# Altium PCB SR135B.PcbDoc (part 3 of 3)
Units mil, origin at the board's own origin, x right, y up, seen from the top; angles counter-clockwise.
Board outline 4100 x 3600 mil, 4 copper layers (Top Layer, Signal Layer 1, Signal Layer 2, Bottom Layer), stack 73.068 mil thick; 169 components, 61 nets, 392 pads, 261 vias.
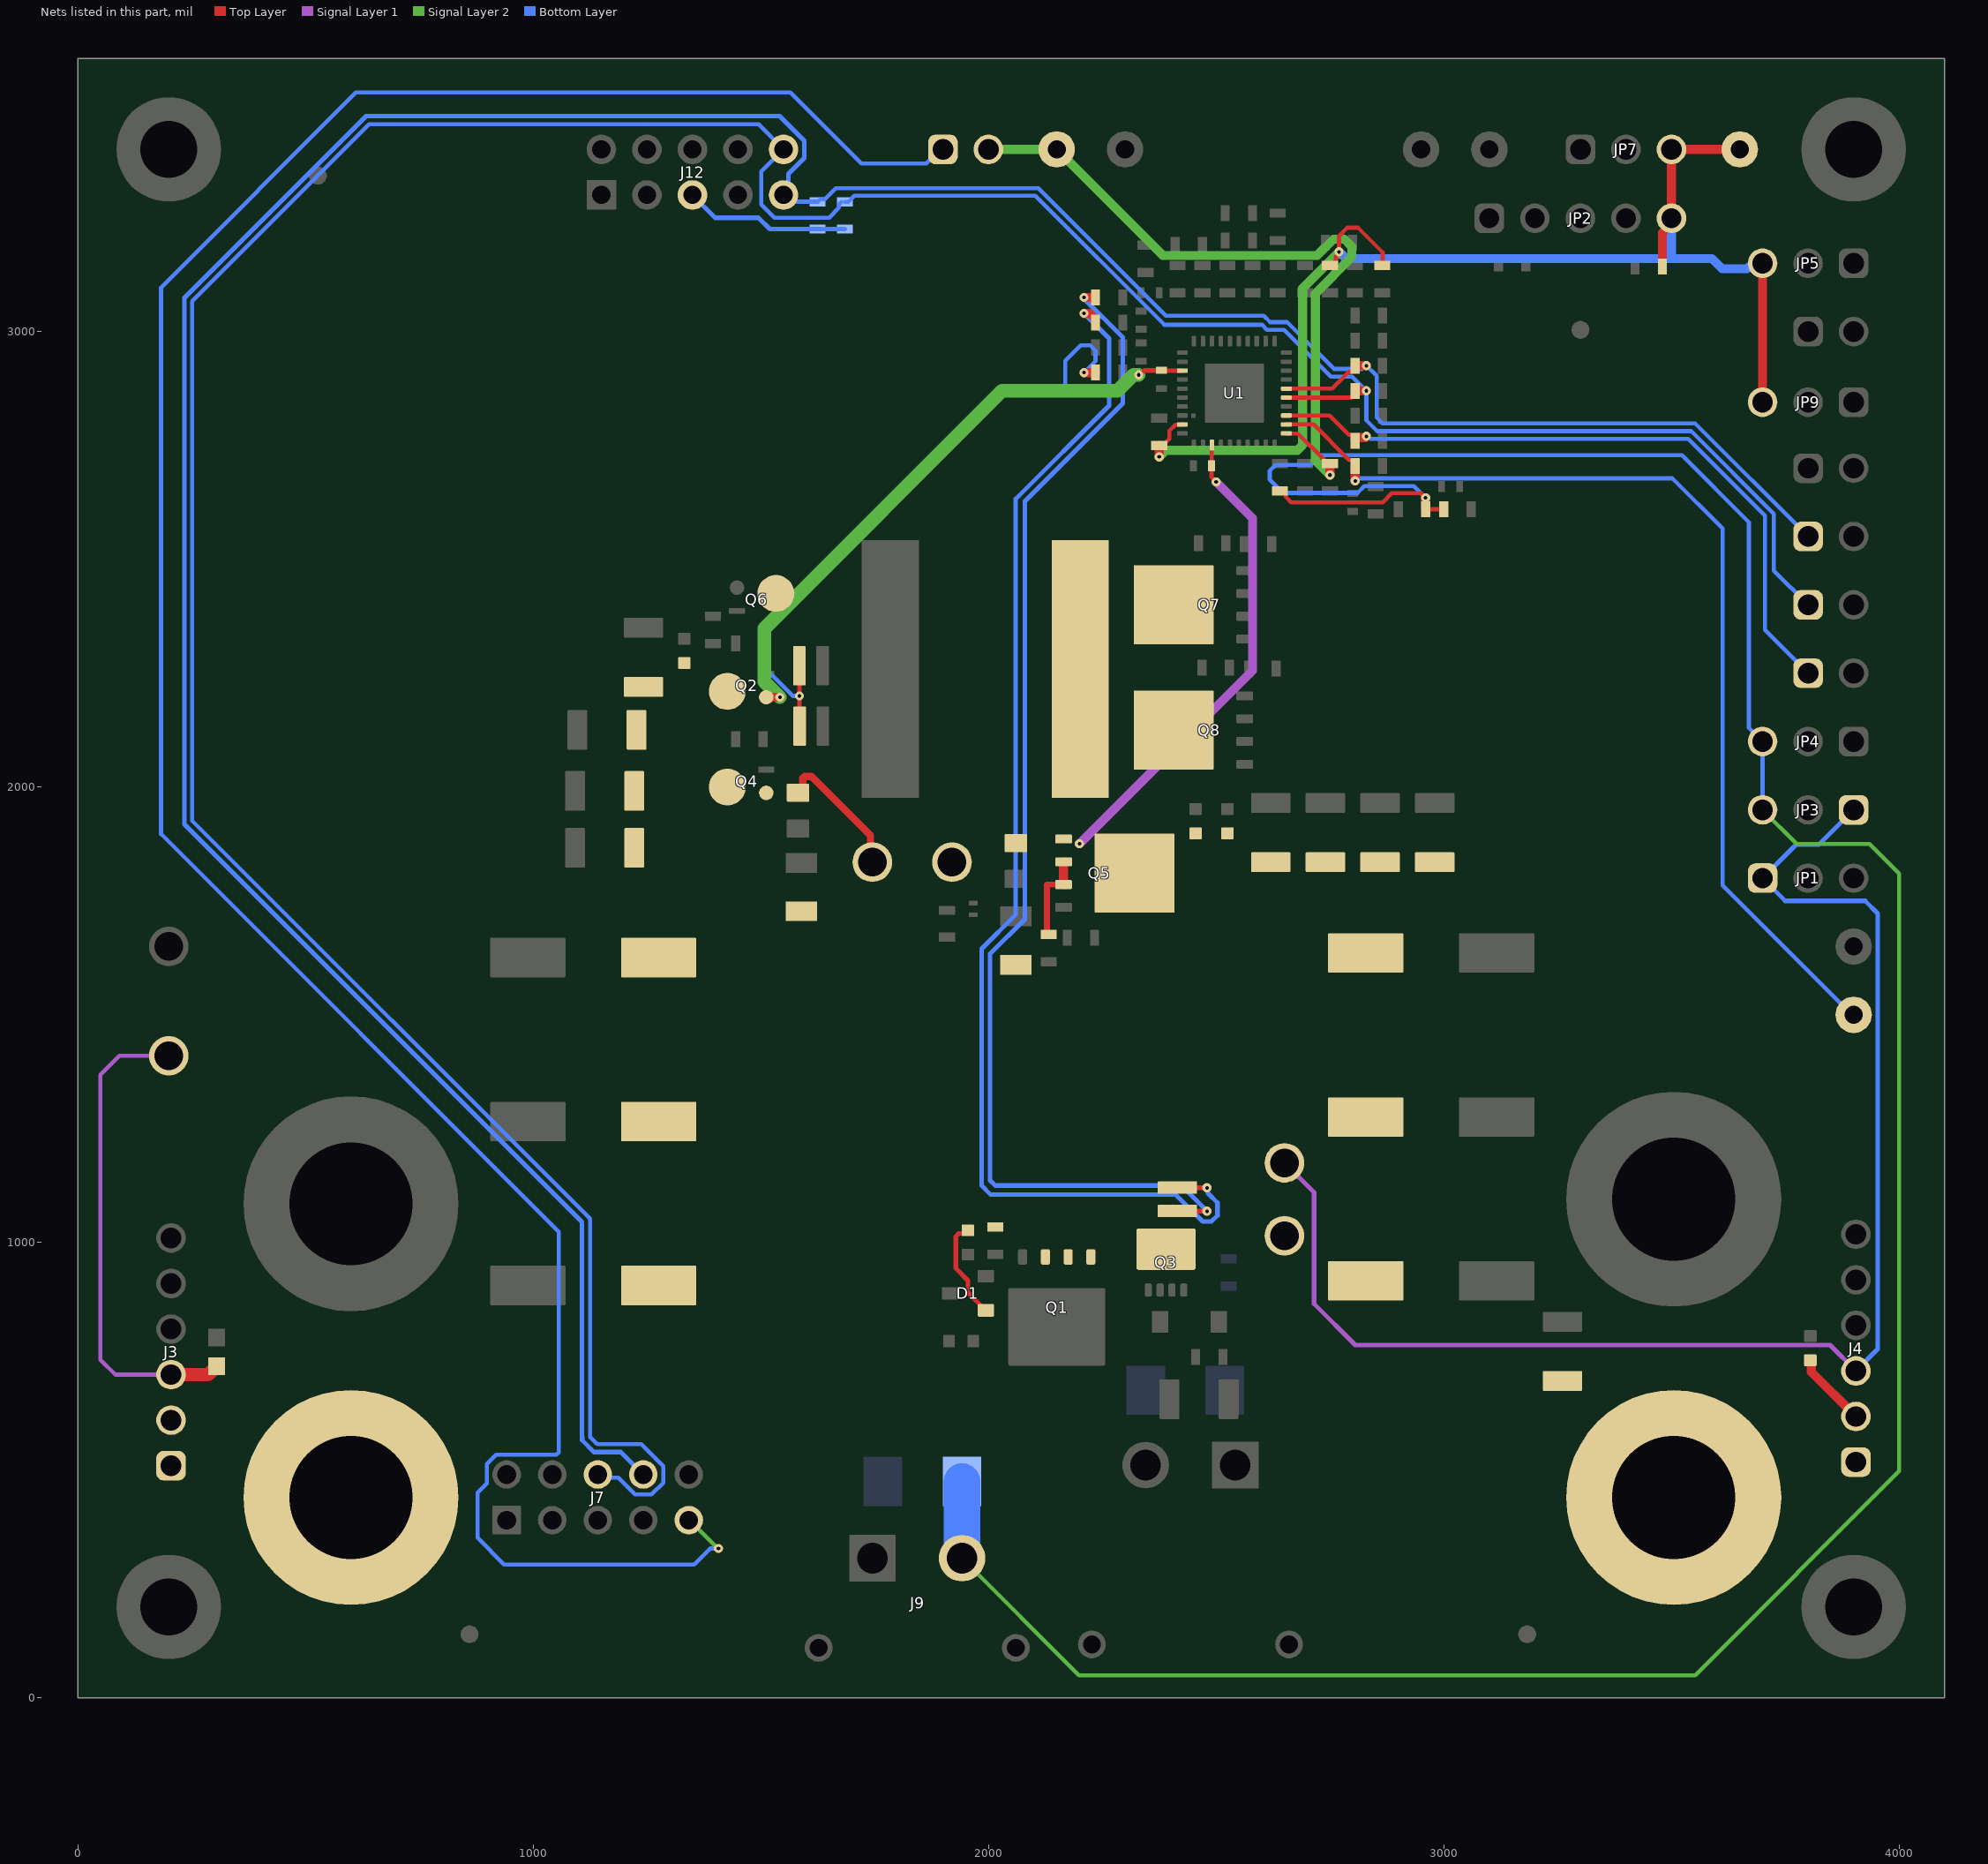
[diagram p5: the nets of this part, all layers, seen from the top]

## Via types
v1: diameter 20, hole 8, Top Layer to Bottom Layer, tented both sides, 241 vias
v2: diameter 19.68, hole 7.87, Top Layer to Bottom Layer, tented both sides, 12 vias
v3: diameter 24, hole 8, Top Layer to Bottom Layer, tented both sides, 7 vias
v4: diameter 34, hole 16, Top Layer to Bottom Layer, tented both sides, 1 vias

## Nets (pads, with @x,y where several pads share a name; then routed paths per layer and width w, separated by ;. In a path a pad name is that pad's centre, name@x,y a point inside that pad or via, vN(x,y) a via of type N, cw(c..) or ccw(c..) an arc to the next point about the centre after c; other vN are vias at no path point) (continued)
SCL: J7.8 J12.9 JP11.1 R39.1 R42.2 U1.6 | length 7567.3
  Top Layer w9: U1.6@2654.17,2874.84 2754.84,2874.84 2792,2912 2799.5,2912 2805,2917.5 R42.2@2805,2925
  Top Layer w20: R42.2@2805,2925 v1(2830,2925)
  Bottom Layer w9: R39.1@1625,3285 1630.5,3290.5 1640.46,3290.5 1664.96,3315 2110,3315 2390,3035 2604.49,3035 2618.74,3020.75 2656.13,3020.75 2758.76,2918.13 2820.15,2918.13 2827.02,2925 v1(2830,2925) 2852.37,2902.63 2852.37,2811.49 2865.62,2798.25 3551.75,2798.25 JP11.1@3800,2550
  Bottom Layer w10: J7.8@1242.09,490.59 1192.68,540 1133.71,540 1107.63,566.09 1107.63,574.5 1107.37,574.75 1107.37,1044.94 234.25,1918.07 234.25,3073.82 633.44,3473.01 1541.13,3473.01 1595.35,3418.79 1595.35,3381.21 1560.52,3346.38 1560.52,3310.52 J12.9@1550,3300 1564.87,3300 1579.87,3285 R39.1@1625,3285
SDA: J7.6 J12.10 JP10.1 R40.1 R41.2 U1.5 | length 7872.1
  Top Layer w9: U1.5@2654.17,2855.16 2797.66,2855.16 2805,2862.5 R41.2@2805,2870
  Top Layer w20: R41.2@2805,2870 v1(2830,2870)
  Bottom Layer w9: J7.6@1142.09,490.59 1148.65,484.03 1186.89,484.03 1224,446.92 1260.18,446.92 1285.76,472.5 1285.76,509.24 1237.63,557.37 1141.87,557.37 1141.12,558.13 1140.16,558.13 1125,573.28 1125,1052.5 251.62,1925.88 251.62,3066.62 640,3455 1495,3455 J12.10@1550,3400 1501.25,3351.25 1501.25,3278.75 1530,3250 1650,3250 1672,3272 1672,3279.5 R40.1@1677.5,3285 ; R40.1@1685,3285 1692.5,3285 1705.63,3298.13 2103.01,3298.13 2386.14,3015 2600.63,3015 2611.75,3003.88 2649.14,3003.88 2751.77,2901.25 2798.75,2901.25 v1(2830,2870) 2830,2805 2853.63,2781.37 3543.63,2781.37 3725,2600 3725,2475 JP10.1@3800,2400
SS/ATRK: C37.1 TP13.1 U1.2 | length 2269.5
  Top Layer w9: U1.2@2654.17,2796.1 2713.9,2796.1 2792,2718 2799.5,2718 2805,2712.5 C37.1@2805,2705
  Top Layer w20: C37.1@2805,2705 2805,2672.72 v1(2805.45,2672.26)
  Bottom Layer w9: v1(2805.45,2672.26) 2808.43,2672.26 2813.93,2677.76 3501.9,2677.76 3612.07,2567.59 3612.07,1784.07 3896.14,1500 TP13.1@3900,1500
SW1: C30.2 C31.1 Q2.1-2-3 Q4.1-2-3 Q6.5-6-7-8 R4.2 R6.2 R17.2 TP5.1 U1.23 | length 3098.9
  Top Layer w10: R6.2@1584.71,2266.3 1585,2266.01 v1(1585,2200) 1585,2133.99 R4.2@1585.29,2133.7 ; TP5.1@1740.79,1839.21 TP5.1@1745,1835 ; v1(2330,2905) 2332.71,2905 2342.33,2914.63 2379.63,2914.63 C31.1@2380,2915 2380.71,2914.29 2425.75,2914.29 U1.23@2425.83,2914.21
  Top Layer w16: C30.2@1581.75,1975.58 1592.42,1986.25 1592.42,2019.27 1596.58,2023.43 1610.87,2023.43 1740.79,1893.5 TP5.1@1740.79,1839.21
  Top Layer w20: Q2.1-2-3@1512.09,2197.2 v1(1542.09,2197.2) ; v1(2210,2910) R17.2@2235,2910
  Signal Layer 2 w30: v1(1542.09,2197.2) 1507.87,2231.42 1507.87,2347.87 2030,2870 2283.51,2870 2318.51,2905 v1(2330,2905)
  Bottom Layer w9: v1@1584.82,2200.18 1569.82,2200.18 1500,2270 1500,2351.97 2027.09,2879.06 2163.35,2879.06 2168.62,2884.34 2168.62,2935.97 2202.65,2970 2223.45,2970 2235,2958.45 2235,2935 v1(2210,2910)
  Bottom Layer w10: v1@1584.82,2200.18 v1(1585,2200)
SW2: C32.2 C33.1 C42.1 L1.2 Q5.1 Q5.2 Q5.3 Q7.5-6-7-8 Q8.5-6-7-8 TP6.1 U1.33 | length 1266.9
  Top Layer w9: U1.33@2490.79,2750.83 2490.39,2750.43 2490.39,2705.39 C33.1@2490,2705 2490,2680.35 2500,2670.35 v1(2500,2670)
  Top Layer w13: C42.1@2128.34,1676.57 2128.34,1785.87 Q5.3@2165.12,1785.87 ; C42.1@2132,1676.23 C42.1@2132.34,1676.57
  Top Layer w20: Q5.3@2165.12,1785.87 Q5.2@2165.12,1835.87
  Signal Layer 1 w20: v1(2200,1875.48) 2580,2255.48 2580,2590 v1(2500,2670)
SYNC: JP6.1 R24.2 U1.3 | length 1536.9
  Top Layer w9: U1.3@2654.17,2815.79 2749.21,2815.79 2792,2773 2799.5,2773 R24.2@2805,2767.5
  Top Layer w20: R24.2@2805,2760 2805,2767.5 2827.5,2767.5 v1(2830,2770)
  Bottom Layer w9: v1(2830,2770) 2832.98,2770 2838.48,2764.5 3536.64,2764.5 3705,2596.14 3705,2345 JP6.1@3800,2250
VBUS: J12.5 R39.2 R40.2 | length 366.1
  Bottom Layer w10: J12.5@1350,3300 1400,3250 1495,3250 1520,3225 R39.2@1625,3225 R40.2@1685,3225
VCC1: C26.2 JP12.2 TP10.1 U1.1 | length 1614.2
  Top Layer w9: U1.1@2654.17,2776.42 2679.48,2776.42 2737,2718.9 2737,2715.5 2742.5,2710 C26.2@2750,2710
  Top Layer w20: v1(2750,2685) C26.2@2750,2710
  Signal Layer 2 w20: JP12.2@2000,3400 TP10.1@2150,3400 2382.87,3167.13 2722.13,3167.13 2757.87,3202.87 2781.55,3202.87 2797.87,3186.55 2797.87,3163.45 2717.87,3083.45 2717.87,2717.13 v1(2750,2685)
VCC1_J: J7.9 JP12.1 | length 5888.6
  Signal Layer 2 w9: J7.9@1342.09,390.59 1343.33,390.59 1405.8,328.13 v1(1407.05,328.13)
  Bottom Layer w9: v1(1407.05,328.13) 1389.11,328.13 1354.11,293.13 936.69,293.13 878.13,351.69 878.13,450.49 898.41,470.78 898.41,513.41 919.26,534.26 1050.73,534.26 1050.98,534.01 1056.25,539.28 1056.25,1023.77 183.13,1896.89 183.13,3096.99 611.14,3525 1565,3525 1721.25,3368.75 1863.48,3368.75 1894.73,3400 JP12.1@1900,3400
VCC2: C27.2 JP2.5 JP5.3 JP7.3 JP9.3 R2.2 R25.2 R36.1 TP9.1 U1.29 | length 2882.7
  Top Layer w9: C27.2@2375,2750 2382.5,2750 2397.37,2764.87 2397.37,2782.44 2410.62,2795.68 2425.41,2795.68 U1.29@2425.83,2796.1 ; R25.2@2750,3145 2757.5,3145 2763,3150.5 2763,3165.02 2770,3172.02 v1(2770,3175) 2770,3210.31 2787.81,3228.13 2811.56,3228.13 2865.82,3173.87 2865.82,3145.82 R36.1@2865,3145
  Top Layer w20: v1(2375,2725) C27.2@2375,2750 ; R2.2@3480,3143 3480,3216.69 3500,3236.69 JP2.5@3500,3248.86 JP7.3@3500,3400 TP9.1@3650,3400 ; JP9.3@3700,2845 JP5.3@3700,3150
  Signal Layer 2 w20: v1(2375,2725) 2389.59,2739.59 2678.28,2739.59 2690,2751.31 2690,3095 v1(2770,3175)
  Bottom Layer w20: v1(2770,3175) 2784.67,3160.33 3493.31,3160.33 ; JP2.5@3500,3248.86 3500,3167.02 3493.31,3160.33 ; JP5.3@3700,3150 3691.4,3141.4 3669.25,3141.4 3665.8,3137.96 3610.9,3137.96 3588.53,3160.33 3493.31,3160.33
VIN: C9.2 C11.1 C12.1 C14.2 C17.2 C18.2 C19.2 C20.2 C40.2 D3.1 J2.1 J3.1 J3.2 J3.3 J9.2 JP3.3 JP4.3 Q2.5-6-7-8 Q4.5-6-7-8 R7.2 R21.2 R23.2 R35.2 TP3.1 | length 7831.8
  Top Layer w9: R35.2@2640,2650 2647.5,2650 2653,2644.5 2653,2637 2665,2625 2866,2625 2886,2645 2949.23,2645 2959.23,2635 v1(2960,2635) ; R21.2@2960,2610 R7.2@3000,2610
  Top Layer w20: R21.2@2960,2610 v1(2960,2635)
  Top Layer w30: J3.3@205,710 286.5,710 300.31,723.82 301.3,723.82 305,727.52 C11.1@305,728.5
  Signal Layer 1 w9: TP3.1@200,1410 91.83,1410 50,1368.17 50,742.52 82.52,710 J3.3@205,710
  Signal Layer 2 w9: J9.2@1942.09,306.98 2199.07,50 3552,50 4000,498 4000,1810 3935,1875 3775,1875 JP3.3@3700,1950
  Bottom Layer w9: v1(2960,2635) 2934.09,2660.89 2825.72,2660.89 2810.58,2645.75 2647.61,2645.75 2617.63,2675.73 2617.63,2694.27 2630.73,2707.37 2707.37,2707.37 2728.39,2728.39 3522.87,2728.39 3670,2581.25 3670,2130 JP4.3@3700,2100 JP3.3@3700,1950
  Bottom Layer w80: J9.2@1942.09,306.98 D3.1@1942.09,475.59
VOUT: C1.2 C3.2 C4.2 C8.2 D1.1 J1.1 J4.1 J4.2 Q1.1 Q1.2 Q1.3 Q3.5 Q3.6 Q3.7 Q3.8 Q3.9@2390,985.47 R1.2 R3.2 R16.2 TP2.1 | length 3075.6
  Top Layer w10: C1.2@1955,1026.58 1948.38,1019.96 1934.96,1019.96 1928.35,1013.35 1928.35,943.32 1955.16,916.5 1955.16,890.27 D1.1@1994.37,851.06 ; R3.2@2415,1069.41 2415.3,1069.11 2479.7,1069.11 v1(2480,1068.82)
  Top Layer w20: v1(2210,3075) R16.2@2235,3075 ; C8.2@3805,741.5 3807.23,739.27 3807.23,715.84 J4.2@3905,618.07
  Bottom Layer w10: v1(2210,3075) 2210,3072.35 2295,2987.35 2295,2842.36 2080,2627.36 2080,1710 2003.74,1633.74 2003.74,1136.26 2015,1125 2423.82,1125 v1(2480,1068.82)
VOUT1: C5.2 C6.2 C7.2 C10.2 C13.2 C21.2 C22.2 C23.2 J4.3 JP1.1 JP3.1 Q5.5-6-7-8 R3.1 R15.2 R26.2 TP1.1 | length 5941.9
  Top Layer w10: R3.1@2415,1120.59 2415.3,1120.3 2479.7,1120.3 v1(2480,1120)
  Top Layer w20: v1(2210,3040) 2210.37,3039.63 2222.87,3039.63 2235,3027.5 R15.2@2235,3020
  Signal Layer 1 w10: TP1.1@2650,1175 2715,1110 2715,865.49 2805.49,775 3848.07,775 J4.3@3905,718.07
  Bottom Layer w10: v1(2210,3040) 2265,2985 2265,2837.64 2060,2632.64 2060,1719.96 1985,1644.96 1985,1125 2005,1105 2411.47,1105 2470.53,1045.95 2489.47,1045.95 2502.87,1059.34 2502.87,1087.4 2481.91,1108.36 2481.91,1118.09 v1(2480,1120) ; JP3.1@3900,1950 3823.48,1873.48 3773.48,1873.48 JP1.1@3700,1800 3750,1750 3925.43,1750 3952.87,1722.56 3952.87,765.94 J4.3@3905,718.07
pads on no net: FID1.1 FID2.1 FID3.1 FID4.1 H1.1 H2.1 H3.1 H4.1 J12.1 J12.2 J12.3 J12.4 J12.7 J12.8 Q1.9@2056.59,890.08 Q1.9@2097.64,787.91 Q1.9@2097.64,833.19 Q1.9@2097.64,878.46 Q1.9@2150,787.91 Q1.9@2150,827.87 Q1.9@2150,833.19 Q1.9@2150,878.46 Q1.9@2202.36,787.91 Q1.9@2202.36,833.19 Q1.9@2202.36,878.46 Q1.9@2243.41,890.08 Q3.9@2328.98,948.46 Q3.9@2367.56,971.5 Q3.9@2390,948.46 Q3.9@2390,977.4 Q3.9@2412.44,971.5 Q3.9@2451.02,948.46 U1.26 U1.34 U1.39

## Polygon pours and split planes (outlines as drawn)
VOUT on Top Layer "TOP_LAYER_VOUT_P007" (solid, remove dead copper, pour order 7): 1900.39,1085 1900.39,1005.22 2085.19,1004.83 2085.49,865 2541.87,869.46 2541.87,732.61 2638.84,732.61 2639.53,204.45 ccw(c2679.05,210.5) 2685.1,170.98 2720.69,161.96 2720.69,26.36 4073.49,26.51 4074.51,758.23 2952,758.23 2952,1074.06 ccw(c2941.06,1074.06) 2941.06,1085
GND on Top Layer "TOP_LAYER_GND_P017" (solid, remove dead copper, pour order 17): 0,0 0,3600 4100,3600 4100,0
PPHV on Top Layer "TOP_LAYER_PPHV_P006" (solid, remove dead copper, pour order 6): 2465,920 2023.69,920 2023.69,773.69 1935,685 2050,570 2050,151.18 2049.41,150.59 2050,150 2465,150 2465,440
VOUT1 on Top Layer "TOP_LAYER_VOUT1_P008" (solid, remove dead copper, pour order 8): 2960,1105 2960,1711.64 3035,1786.64 3035,1855.42 2975.42,1915 2284.22,1915 2049.22,1680 1985.32,1680.07 1985.32,1655 1900,1655 1900,1105
AGND on Top Layer "TOP_LAYER_AGND_P000" (solid, remove dead copper, pour order 0): 4100,3600 2250,3600 2250,3300 2465,3085 2465,2790 2535,2790 2640,2685 2640,2650 3525,2650 3610,2565 3610,2155 3855,2155 3855,1900 4100,1900
VIN on Top Layer "TOP_LAYER_VIN_P005" (solid, remove dead copper, pour order 5): 0,750 0,0 1577.09,0 1577.09,150.59 2049.41,150.59 2050,150 2050,570 1880,740 1880,1614.41 1654.41,1840 1555,1840 1555,1872.89 1475,1952.89 1475,2285 1209.4,2285 1180,2255.6 1180,905 1025,750
SW2 on Top Layer "TOP_LAYER_SW2_P004" (solid, remove dead copper, pour order 4): 1875,2620 1924.98,2669.98 2520,2669.98 2520,2055 2420,1955 2420,1925 2320,1925 2300,1905 2300,1762.06 1875,1762.06
NetL1_1 on Top Layer "TOP_LAYER_NETL1_1_P002" (solid, remove dead copper, pour order 2): 1605,2465 1690,2550 1855,2550 1855,1970 1717.22,1970 1605,2082.22
SW1 on Top Layer "TOP_LAYER_SW1_P001" (solid, remove dead copper, pour order 1): 1495,1950 1605,1950 1605,2465 1560,2510 1550,2500 1462.57,2500 1448.27,2485.7 1448.27,2406.73 1507.5,2347.5 1495,2335
GND on Signal Layer 1 "SIGNAL_LAYER_1_GND_P013" (solid, remove dead copper, pour order 13): 0,0 0,3600 4100,3600 4100,0
AGND on Signal Layer 1 "SIGNAL_LAYER_1_AGND_P010" (solid, remove dead copper, pour order 10): 4100,3600 2250,3600 2250,3300 2465,3085 2465,2790 2535,2790 2640,2685 2640,2650 3525,2650 3610,2565 3610,2155 3855,2155 3855,1900 4100,1900
SW1 on Signal Layer 2 "SIGNAL_LAYER_2_SW1_P012" (solid, remove dead copper, pour order 12): 1542.04,2182.24 1542.04,2227.96 1605,2227.96 1605,2445 1520,2445 1429.74,2354.74 1429.74,2224.04 1471.55,2182.24
GND on Signal Layer 2 "SIGNAL_LAYER_2_GND_P016" (solid, remove dead copper, pour order 16): 0,0 0,3600 4100,3600 4100,0
AGND on Signal Layer 2 "SIGNAL_LAYER_2_AGND_P015" (solid, remove dead copper, pour order 15): 4100,3600 2250,3600 2250,3300 2465,3085 2465,2790 2535,2790 2640,2685 2640,2650 3525,2650 3610,2565 3610,2155 3855,2155 3855,1900 4100,1900
GND on Bottom Layer "BOTTOM_LAYER_GND_P014" (solid, remove dead copper, pour order 14): 0,0 0,3600 4100,3600 4100,0
AGND on Bottom Layer "BOTTOM_LAYER_AGND_P011" (solid, remove dead copper, pour order 11): 4100,3600 2250,3600 2250,3300 2465,3085 2465,2790 2535,2790 2640,2685 2640,2650 3525,2650 3610,2565 3610,2155 3855,2155 3855,1900 4100,1900

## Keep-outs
Keep-Out Layer:
  text ".Layer_Name" at 577,-858.49 h60

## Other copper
Top Layer:
  rectangle net LO2: 2415,2765 2435,2780
  rectangle net GND: 2310,2800 2365,2820
  rectangle net GND: 1577.09,30 2707.09,150.59
  pour cut-out: 1944.14,1759.07 1943.14,1758.07 1943.14,1699.07 1985.24,1699.07 1991.03,1704.85 1991.03,1758.68
  pour cut-out: 235,115 285,165 285,235 235,285 165,285 115,235 115,165 165,115
  pour cut-out: 3935,115 3985,165 3985,235 3935,285 3865,285 3815,235 3815,165 3865,115
  pour cut-out: 3935,3315 3985,3365 3985,3435 3935,3485 3865,3485 3815,3435 3815,3365 3865,3315
  pour cut-out: 235,3315 285,3365 285,3435 235,3485 165,3485 115,3435 115,3365 165,3315
  text ".Layer_Name" at 577,-858.49 h60
Signal Layer 1:
  pour cut-out: 1395,2309.7 1454.7,2309.7 1460,2315 1454.96,2320.04 1395,2320.04
  pour cut-out: 235,115 285,165 285,235 235,285 165,285 115,235 115,165 165,115
  pour cut-out: 3935,115 3985,165 3985,235 3935,285 3865,285 3815,235 3815,165 3865,115
  pour cut-out: 3935,3315 3985,3365 3985,3435 3935,3485 3865,3485 3815,3435 3815,3365 3865,3315
  pour cut-out: 235,3315 285,3365 285,3435 235,3485 165,3485 115,3435 115,3365 165,3315
  text ".Layer_Name" at 577,-858.49 h60
Signal Layer 2:
  pour cut-out: 1530,2460 1618.51,2460 1618.51,2363.51 2070,2815 2379.54,2815 2376.17,2847.81 2365.3,2865 2365.3,2905 2313.72,2940.3 2254.23,2940.3 2237.96,2956.58 2026.58,2956.58
  pour cut-out: 3935,3315 3985,3365 3985,3435 3935,3485 3865,3485 3815,3435 3815,3365 3865,3315
  pour cut-out: 235,115 285,165 285,235 235,285 165,285 115,235 115,165 165,115
  pour cut-out: 235,3315 285,3365 285,3435 235,3485 165,3485 115,3435 115,3365 165,3315
  text ".Layer_Name" at 577,-858.49 h60
Bottom Layer:
  pour cut-out: 1445,2375 1445,2269.52 1514.61,2198.58 1665,2202 1665,2410 2070,2815 2379.54,2815 2376.17,2847.81 2365.3,2865 2365.3,2905 2313.72,2940.3 2254.23,2940.3 2237.96,2956.58 2026.58,2956.58
  pour cut-out: 3935,3315 3985,3365 3985,3435 3935,3485 3865,3485 3815,3435 3815,3365 3865,3315
  pour cut-out: 3935,115 3985,165 3985,235 3935,285 3865,285 3815,235 3815,165 3865,115
  pour cut-out: 235,115 285,165 285,235 235,285 165,285 115,235 115,165 165,115
  pour cut-out: 235,3315 285,3365 285,3435 235,3485 165,3485 115,3435 115,3365 165,3315
  text ".Layer_Name" at 577,-858.49 h60

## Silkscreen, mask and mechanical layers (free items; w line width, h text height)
Top Overlay:
  lines w5: 2218.21,3126 2299,3126 2322,3103 ; 2313,2697 2313,2753 2340,2780 2350,2780 ; 2313,2785 2313,2831 2313,2846 2331,2846 2355,2870 2360,2870 ; 2497,3012 2497,3378 ; 2497,3167.13 2665,3167.13 ; 2665,3060 2665,3167.13 ; 2665,3378 2665,3167.13
  text "VCC1" at 2106,3506 h30
  text "AGND" at 2256,3506 h30
  text "AGND" at 2879.53,3506 h30
  text "COMP" at 3059.45,3506 h30
  text "ILIMCOMP" at 3296,3506 h30
  text "VCC2" at 3596.04,3506 h30
  text "AGND   VCC2" at 3269.96,3311.09 h45
  text "VCC1" at 1906,3287.25 h30
  text "USB2ANY / 5: VBUS / 6: GND / 9: SCL / 10:SDA" at 766.98,3251.1 h20
  text "AGND" at 3847.96,3210.73 h45
  text "MODE" at 3522.75,3132.58 h30
  text "FPWM      PSM" at 3660.8,3065.01 h45
  text "CDC" at 3628.03,2984 h30
  text "'.PRJ_Title'" at 284.57,2916.29 h100
  text "AGND" at 3847.96,2906.46 h45
  text "'.PRJ_Number' Rev.:.PCB_Rev" at 280.57,2844 h60
  text "ADDR" at 3508.04,2827.33 h30
  text "1                0" at 3691.4,2758.91 h45
  text "CFG2" at 3598.04,2671.5 h30
  text "AGND" at 3847.96,2611.46 h45
  text "SCL" at 3628.03,2520 h30
  text "AGND" at 3847.96,2458.71 h45
  text "SDA" at 3628.03,2366.49 h30
  text "AGND" at 3847.96,2311.46 h45
  text "SYNC" at 3598.04,2219 h30
  text "AGND" at 3847.96,2159.53 h45
  text "EN/UVLO" at 3418.06,2076 h30
  text "VIN" at 3669.78,2007.5 h45
  text "AGND" at 3847.96,2007.99 h45
  text "BIAS" at 3513.03,1927 h30
  text "VIN" at 3670.04,1857 h45
  text "VOUT1" at 3848.04,1857.49 h45
  text "VOUT" at 3508.04,1780 h30
  text "PS" at 3670,1710.49 h45
  text "PPHV" at 3848,1710 h45
  text "SW1" at 1667.11,1665.03 h30
  text "SW2" at 1778.5,1665.03 h30
  text "nRST" at 3720,1641.54 h30
  text "GND" at 84,1606 h30 r90
  text "SS/ATRK" at 3630,1491.79 h30
  text "GND" at 528.35,1426 h50
  text "GND" at 3438.35,1426 h50
  text "VIN" at 84,1366 h30 r90
  text "Max.14A" at 103.97,1239 h35
  text "Max.5.0A" at 3761,1239 h35
  text "9-36V" at 103.97,1180 h35
  text "5V - 48V" at 3758.06,1180 h35
  text "VOUT1" at 2553.54,1114.27 h30 r90
  text "GND" at 56,1006 h30
  text "GND" at 3966,988.99 h30
  text "VOUT" at 2553.54,955.49 h30 r90
  text "S-" at 88.27,787.65 h30
  text "S-" at 3966,787.54 h30
  text "S+" at 88.52,702.22 h30
  text "S+" at 3966,681.98 h30
  text "VOUT" at 3966,500.03 h30
  text "VIN" at 56,487.13 h30
  text "VIN" at 532.52,81 h50
  text "VOUT" at 3413.36,81 h50
  text "Input" at 1743,72.66 h50
  text "Output" at 2327.1,72.66 h50
  text ".Layer_Name" at 577,-858.49 h60
Bottom Overlay:
  text "GND" at 654.02,1426 h50
  text "GND" at 3570.04,1426 h50
  text "VIN" at 636.99,80.01 h50
  text "VOUT" at 3594,80.01 h50
  text ".Layer_Name" at 577,-858.49 h60
Top Paste:
  text ".Layer_Name" at 577,-858.49 h60
Bottom Paste:
  text ".Layer_Name" at 577,-858.49 h60
Top Solder:
  text ".Layer_Name" at 577,-858.49 h60
  text ".Layer_Name" at 577,-858.49 h60
Bottom Solder:
  text ".Layer_Name" at 577,-858.49 h60
Drill Guide:
  text ".Layer_Name" at 577,-858.49 h60
M1 Board Outline:
  the board outline again, w10
  text ".Layer_Name" at 577,-858.49 h60
M2 Board Dimensions:
  rectangle: 0,-275 125,-150
  rectangle: 125,-400 500,-275
  lines w7: 0,-275 1000,-275 ; 125,-400 125,-150 ; 250,-400 250,-150 ; 500,-400 500,-150 ; 750,-400 750,-150 ; 0,-400 1000,-400 1000,-150 0,-150 0,-400
  text ".Layer_Name" at 577,-858.49 h60
M3 3D STEP Top:
  text ".Layer_Name" at 577,-858.49 h60
M4 3D STEP Bottom:
  text ".Layer_Name" at 577,-858.49 h60
M5 Assembly Top:
  lines w10: -292,-930.17 6308,-930.17 ; -292,-726.83 6310,-726.83 ; -292,-523.5 -292,-1133.5 3713,-1133.5 6310,-1133.5 6310,-523.5 -291.5,-523.5 -291.5,-1133.5 1284,-1133.5 ; 2173,-1133.5 2173,-523.5 ; 3440,-726.83 3440,-523.5 ; 4280,-726.83 4280,-523.5 ; 4902,-1140 4902,-937.17
  text "COMPONENTS MARKED 'DNP' SHOULD NOT BE POPULATED." at 1153.5,-318.5 h60
  text "ASSEMBLY VARIANT:" at 1153,-434 h60
  text ".VariantName" at 2189,-434 h60
  text "PCB VIEWED FROM TOP SIDE" at -228.5,-655.67 h60
  text "BOARD #:" at 2248,-655.67 h60
  text ".PRJ_Number" at 2793.5,-655.67 h60
  text "REV:" at 3638,-655.67 h60
  text ".PCB_Rev" at 3929.5,-655.67 h60
  text "SVN REV:" at 4476,-655.67 h60
  text ".VersionControl_RevNumber" at 4982,-655.67 h60
  text "TID #:" at 2248,-859 h60
  text ".TID" at 2793.5,-859 h60
  text "PLOT NAME =" at -228.5,-1064.34 h60
  text ".plot_File_Name" at 577,-1064.34 h60
  text "GENERATED    :" at 2250,-1064.34 h60
  text ".Print_Date" at 3119.5,-1064.34 h60
  text ".Print_Time" at 3848.5,-1064.34 h60
  text "TEXAS INSTRUMENTS" at 5113,-1064.34 h60
M6 Assembly Bottom:
  lines w10: -292.5,-727.33 6309.5,-727.33 ; -290.5,-930.67 6309.5,-930.67 ; 1115.5,-1140.5 1115.5,-937.67 ; 1737.5,-727.33 1737.5,-524 ; 2577.5,-727.33 2577.5,-524 ; 3844.5,-1134 3844.5,-524 ; 4733.5,-1134 6309,-1134 6309,-524 -292.5,-524 -292.5,-1134 2304.5,-1134 6309.5,-1134 6309.5,-524
  text "COMPONENTS MARKED 'DNP' SHOULD NOT BE POPULATED." at 6102,-318 h60
  text ".VariantName" at 5058,-434 h60
  text "ASSEMBLY VARIANT:" at 6097,-434 h60
  text ".VersionControl_RevNumber" at 1035.5,-656.17 h60
  text "SVN REV:" at 1541.5,-656.17 h60
  text ".PCB_Rev" at 2088,-656.17 h60
  text "REV:" at 2379.5,-656.17 h60
  text ".PRJ_Number" at 3224,-656.17 h60
  text "BOARD #:" at 3769.5,-656.17 h60
  text "PCB VIEWED FROM BOTTOM SIDE" at 6246,-656.17 h60
  text ".TID" at 3224,-859.5 h60
  text "TID #:" at 3769.5,-859.5 h60
  text "TEXAS INSTRUMENTS" at 904.5,-1064.84 h60
  text ".Print_Time" at 2169,-1064.84 h60
  text ".Print_Date" at 2898,-1064.84 h60
  text "GENERATED    :" at 3767.5,-1064.84 h60
  text ".plot_File_Name" at 5440.5,-1064.84 h60
  text "PLOT NAME =" at 6246,-1064.84 h60
M9 Title Sheet:
  drawing of 57 lines, arcs and shapes, not listed
  text "1" at 739.84,8036.5 h70
  text "2" at 3235.5,8036.5 h70
  text "3" at 5724.84,8036.5 h70
  text "4" at 8231.51,8036.5 h70
  text "5" at 10730.5,8036.5 h70
  text "6" at 13235.5,8036.5 h70
  text "A" at -416.5,6893.5 h70
  text "A" at 14383.5,6893.5 h70
  text "B" at -416.5,4513.5 h70
  text "B" at 14383.5,4513.5 h70
  text "C" at -416.5,2138.5 h70
  text "C" at 14383.5,2138.5 h70
  text "PROJECT TITLE:" at 11343.5,277.5 h45
  text ".PRJ_Title" at 11393.5,144.17 h70
  text "DESIGNED FOR:" at 11343.5,-23.5 h45
  text ".PRJ_Customer" at 11393.5,-163.5 h70
  text "D" at -416.5,-231.5 h70
  text "D" at 14383.5,-231.5 h70
  text "FILE NAME:" at 11343.5,-323.5 h45
  text ".PCB_File_Name_No_Path" at 11393.5,-443.5 h70
  text "Texas Instruments (TI) and/or its licensors do not warrant the accuracy or completeness of this specification" at 6374,-605.34 h45
  text "ENGINEER:" at 11343.5,-613.5 h45
  text "LAYOUT BY:" at 12848.5,-613.5 h45
  text "or any information contained therein. TI and/or its licensors do not warrant that this design will meet" at 6329.01,-718 h45
  text ".PRJ_Engineer" at 11393.5,-768.49 h70
  text ".PCB_Layout" at 12899,-768.49 h70
  text "the specifications, will be suitable for your application or fit for any particular purpose, or will operate in" at 6329.01,-830.67 h45
  text ".Layer_Name" at 577,-858.49 h60
  text "ALTIUM DESIGNER VERSION:" at 12848.5,-923.5 h45
  text "an implementation. TI and/or its licensors do not warrant that the design is production worthy. You should" at 6329.01,-943.33 h45
  text "completely validate and test your design implementation to confirm the system functionality for your application." at 6374,-1056 h45
  text ".print_Scale" at 11393.5,-1056.83 h70
  text ".Application_BuildNumber" at 12899,-1056.83 h70
  text "1" at 739.84,-1263.5 h70
  text "2" at 3235.5,-1263.5 h70
  text "3" at 5724.84,-1263.5 h70
  text "4" at 8231.51,-1263.5 h70
  text "5" at 10730.5,-1263.5 h70
  text "6" at 13235.5,-1263.5 h70
M10 Fab Notes:
  drawing of 189 lines, arcs and shapes, not listed
  text "DESIGN INFORMATION" at 12382.02,6356.17 h60
  text "MIN. TRACK WIDTH:" at 11737.46,6224.05 h60
  text "8" at 12833.7,6224.05 h60
  text "MIL" at 12988.46,6224.05 h60
  text "7.874" at 12667.32,6102.36 h60
  text "MIN. CLEARANCE:" at 11737.46,6099.92 h60
  text "MIL" at 12988.46,6099.92 h60
  text "MIN. VIA PAD SIZE:" at 11737.46,5975.8 h60
  text "24" at 12803.71,5975.8 h60
  text "MIL" at 12988.46,5975.8 h60
  text "0.05mm (2MIL)" at 12432.46,5845.9 h60
  text "MINIMUM ANNULAR RING" at 11408.23,5837.67 h60
  text "EXTERNAL" at 13140.46,5837.67 h60
  text "PER" at 11608.23,5727.55 h60
  text "IPC-D-275 CLASS 2 LEVEL C" at 11828.23,5727.54 h60
  text "MIL, HOLES" at 13316.46,5627.07 h60
  text "+/-" at 12924,5618.48 h60
  text "+/-" at 13778,5618.48 h60
  text "REGISTRATION TOLERANCES:" at 11408.23,5617.42 h60
  text "METAL" at 12608,5617.42 h60
  text "5" at 13184.2,5617.42 h60
  text "3" at 14017.2,5617.42 h60
  text "MIL" at 14133.46,5617.42 h60
  text "HOLE SIZE TOLERANCE (UNLESS OTHERWISE SPECIFIED):" at 11408.23,5519.1 h60
  text "+/-" at 13778,5516.23 h60
  text "3" at 14017.2,5515.17 h60
  text "MIL" at 14133.46,5515.17 h60
  text "MATERIAL:" at 11333.46,5377.52 h60
  text "FR-4 High Tg" at 12319.9,5249 h60
  text "X" at 12175.46,5241.01 h60
  text "FR-4" at 11754.46,5236.49 h60
  text "OTHER" at 13242.46,5236.49 h60
  text "62 MIL (1.6mm) +/-10%" at 12074.56,5093.46 h60
  text "X" at 11954.46,5091.01 h60
  text "THICKNESS:" at 11408.23,5085.24 h60
  text "OTHER" at 13359.46,5085.24 h60
  text "TOLERANCE:" at 11408.23,4946.92 h60
  text "X" at 12256.46,4946.92 h60
  text "ANSI IPC-6012 TYPE 3 CLASS 2" at 12434.48,4946.92 h60
  text "OTHER +/-" at 12434.46,4802.73 h60
  text "BOW & TWIST:" at 11408.23,4657.54 h60
  text "X" at 12256.46,4657.54 h60
  text "ANSI IPC-6012 TYPE 3 CLASS 2" at 12434.48,4657.54 h60
  text "OTHER +/-" at 12434.46,4510.85 h60
  text "DRILLING:" at 11333.46,4380.23 h60
  text "NC_DRILL FILES" at 13094.46,4275.04 h60
  text "REFERENCE:" at 11408.23,4271.1 h60
  text "X" at 12065.46,4271.01 h60
  text "AS SHOWN" at 12243.46,4271.1 h60
  text "X" at 12966.46,4271.1 h60
  text "OTHER" at 13392.46,4128.85 h60
  text "PTH COPPER THICKNESS:" at 11407.91,4125.32 h60
  text "X" at 12547.14,4125.32 h60
  text "20-30 um" at 12675.14,4125.32 h60
  text "BOARD FINISH:" at 11333.46,3977.73 h60
  text "SILKSCREEN:" at 11488.68,3867.6 h60
  text "X" at 12446.46,3867.6 h60
  text "TOP" at 12563.46,3867.6 h60
  text "X" at 12956.46,3867.6 h60
  text "BOTTOM" at 13074.46,3867.6 h60
  text "SILKSCREEN COLOR:" at 11488.68,3712.41 h60
  text "X" at 12445.46,3712.41 h60
  text "WHITE" at 12563.46,3712.41 h60
  text "OTHER" at 13074.46,3712.41 h60
  text "X" at 12576.46,3568.96 h60
  text "GREEN" at 12694.46,3568.96 h60
  text "OTHER" at 13312.46,3568.96 h60
  text "SOLDER RESIST COLOR:" at 11488.68,3562.1 h60
  text "X" at 12576.46,3414.71 h60
  text "MATTE" at 12694.46,3414.71 h60
  text "SEMI-GLOSS" at 13312,3414.07 h60
  text "IMMERSION GOLD (ENIG)" at 12394.46,3241.94 h60
  text "ENEPIG" at 13732,3234.72 h60
  text "SURFACE FINISH:" at 11333.46,3233.72 h60
  text "X" at 12216.46,3233.72 h60
  text "IMM. TIN/SILVER OR EQUIV" at 11663,3096.4 h60
  text "OTHER" at 13094.46,3092.47 h60
  text "ARRAY/PANEL:" at 11333.46,2937.09 h60
  text "CUT AND TRIM PER M1 BOARD OUTLINE" at 12394.46,2928.87 h60
  text "N.C. ROUTE" at 12394.46,2792.9 h60
  text "X" at 13082.46,2792.9 h60
  text "V. SCORE" at 13260.46,2792.9 h60
  text "CERTIFICATION:" at 11333.46,2663.77 h60
  text "MATERIALS AND WORKMANSHIP FOR ALL PCBS" at 12058.46,2663.77 h60
  text "TO MEET OR EXCEED THE REQUIREMENTS OF:" at 12058.46,2569.71 h60
  text "X" at 11695.97,2441.08 h60
  text "ANSI IPC-A-600F CLASS ->" at 11823.96,2441.08 h60
  text "X" at 13471.97,2441.08 h60
  text "2" at 13581.96,2441.08 h60
  text "1" at 13266.96,2439.58 h60
  text "3" at 13935.96,2439.58 h60
  text "X" at 12507.97,2293.39 h60
  text "RoHS" at 12635.96,2293.39 h60
  text "OTHER" at 13280.36,2293.39 h60
  text "PER ORDER" at 13677.42,2293.39 h60
  text "ALL BOARDS MUST MEET OR EXCEED UL94-V0 REQUIREMENTS." at 11361,2139.57 h60
  text "PCB MUST BEAR THE UL94V-0 UL REGISTERED MATERIAL ID NUMBER" at 11361,2023.5 h60
  text "ADDITIONAL REQUIREMENTS:" at 11333.46,1854.08 h60
  text "MICROSECTION:" at 11408.23,1746.95 h60
  text "YES" at 12313.96,1746.95 h60
  text "REQUIRED" at 13175.46,1602.62 h60
  text "BARE BOARD ELEC. TEST:" at 11408.23,1599.76 h60
  text "NONE" at 12713.96,1599.76 h60
  text "X" at 13057.46,1599.76 h60
  text "PER ORDER" at 13767.46,1599.76 h60
  text "XX MIL VIAS REQUIRE NON-CONDUCTIVE FILL AND PLANARIZE" at 11576.38,1394.82 h59
  text "XX MIL VIAS REQUIRE CONDUCTIVE FILL AND PLANARIZE" at 11584.38,1290.84 h60
  text "OUTER XX MIL TRACES REQUIRE 50 OHM SINGLE-ENDED IMPEDANCE" at 11583.39,1127.46 h58
  text "LAYER 2 & 3 (INNER LAYERS) XX MIL WIDE, XX MIL SPACE / TRACES REQUIRE 100 OHM DIFFERENTIAL IMPEDANCE" at 11575.39,891.74 h60
  text ".Layer_Name" at 577,-858.49 h60
M11 Gerber Information:
  lines w10: -292,-930.17 6308,-930.17 ; -292,-726.83 6310,-726.83 ; -292,-523.5 -292,-1133.5 3713,-1133.5 6310,-1133.5 6310,-523.5 -291.5,-523.5 -291.5,-1133.5 1284,-1133.5 ; 2173,-1133.5 2173,-523.5 ; 3440,-726.83 3440,-523.5 ; 4280,-726.83 4280,-523.5 ; 4902,-1140 4902,-937.17
  text "ALL ARTWORK VIEWED FROM TOP SIDE" at -228.5,-655.67 h60
  text "BOARD #:" at 2248,-655.67 h60
  text ".PRJ_Number" at 2793.5,-655.67 h60
  text "REV:" at 3638,-655.67 h60
  text ".PCB_Rev" at 3929.5,-655.67 h60
  text "SVN REV:" at 4476,-655.67 h60
  text ".VersionControl_RevNumber" at 4982,-655.67 h60
  text "LAYER NAME =" at -228.5,-858.49 h60
  text "TID #:" at 2248,-859 h60
  text ".TID" at 2793.5,-859 h60
  text "PLOT NAME =" at -228.5,-1064.34 h60
  text ".plot_File_Name" at 577,-1064.34 h60
  text "GENERATED    :" at 2250,-1064.34 h60
  text ".Print_Date" at 3119.5,-1064.34 h60
  text ".Print_Time" at 3848.5,-1064.34 h60
  text "TEXAS INSTRUMENTS" at 5113,-1064.34 h60
M12 Stackup:
  drawing of 295 lines, arcs and shapes, not listed
  text "Layer" at 9821.59,7874.94 h60
  text "Name" at 10231.51,7874.94 h60
  text "Material" at 11171.25,7874.94 h60
  text "Thickness" at 12031.02,7874.94 h60
  text "Constant" at 12680.85,7874.94 h60
  text "Board Layer Stack" at 13250.71,7874.94 h60
  text "Top Overlay" at 10231.51,7754.94 h60
  text "Top Solder" at 10231.51,7634.94 h60
  text "Solder Resist" at 11171.25,7634.94 h60
  text "0.40mil" at 12031.02,7634.94 h60
  text "3.5" at 12680.85,7634.94 h60
  text "1" at 9821.59,7514.94 h60
  text "Top Layer" at 10231.51,7514.94 h60
  text "2.76mil" at 12031.02,7514.94 h60
  text "Dielectric 1" at 10231.51,7394.94 h60
  text "PP-006" at 11171.25,7394.94 h60
  text "2.80mil" at 12031.02,7394.94 h60
  text "4.1" at 12680.85,7394.94 h60
  text "2" at 9821.59,7274.94 h60
  text "Signal Layer 1" at 10231.51,7274.94 h60
  text "CF-004" at 11171.25,7274.94 h60
  text "1.38mil" at 12031.02,7274.94 h60
  text "Dielectric1" at 10231.51,7154.94 h60
  text "FR-4 High Tg" at 11171.25,7154.94 h60
  text "59.20mil" at 12031.02,7154.94 h60
  text "4.8" at 12680.85,7154.94 h60
  text "3" at 9821.59,7034.94 h60
  text "Signal Layer 2" at 10231.51,7034.94 h60
  text "CF-004" at 11171.25,7034.94 h60
  text "1.38mil" at 12031.02,7034.94 h60
  text "Dielectric 2" at 10231.51,6914.94 h60
  text "PP-006" at 11171.25,6914.94 h60
  text "2.80mil" at 12031.02,6914.94 h60
  text "4.1" at 12680.85,6914.94 h60
  text "4" at 9821.59,6794.94 h60
  text "Bottom Layer" at 10231.51,6794.94 h60
  text "2.76mil" at 12031.02,6794.94 h60
  text "Bottom Solder" at 10231.51,6674.94 h60
  text "Solder Resist" at 11171.25,6674.94 h60
  text "0.40mil" at 12031.02,6674.94 h60
  text "3.5" at 12680.85,6674.94 h60
  text "Bottom Overlay" at 10231.51,6554.94 h60
  text ".Layer_Name" at 577,-858.49 h60
M13 Component Bodies Top:
  text ".Layer_Name" at 577,-858.49 h60
M14 Component Bodies Bottom:
  text ".Layer_Name" at 577,-858.49 h60
M15 Courtyards Top:
  text ".Layer_Name" at 577,-858.49 h60
M16 Courtyards Bottom:
  text ".Layer_Name" at 577,-858.49 h60
Drill Drawing:
  text ".Layer_Name" at 577,-858.49 h60
M17 Embedded Cavity:
  text ".Layer_Name" at 577,-858.49 h60
M18 Embedded Assembly:
  text ".Layer_Name" at 577,-858.49 h60
M19 Embedded Keepout:
  text ".Layer_Name" at 577,-858.49 h60

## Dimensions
0,-400 to 1000,-400 on M2 Board Dimensions
0,3600 to 4100,0 on M2 Board Dimensions
4100,0 to 0,3600 on M2 Board Dimensions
